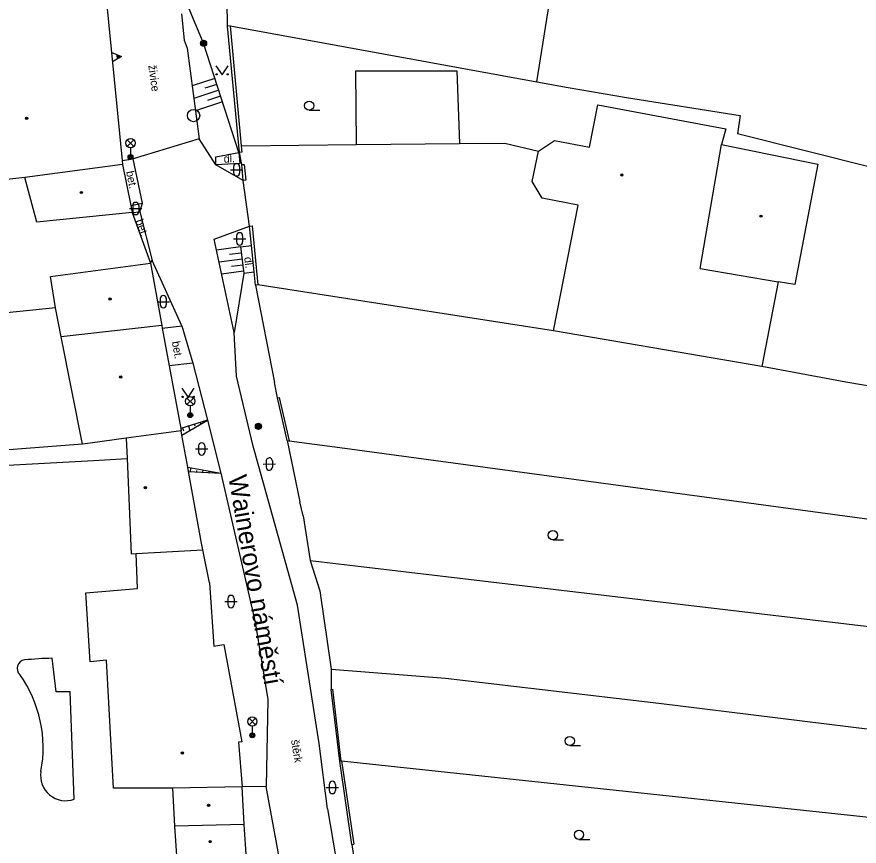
# Model space of a CAD drawing. Extents: x -596024 to -594475, y -1163820 to -1161957.
# Drawn here: x -595951 to -595882.6, y -1163122.3 to -1163055 of the extents above; entities that cross this region are included whole.
import ezdxf

# ---------------------------------------------------------------- set-up
doc = ezdxf.new("R2010")
doc.units = 0
for name, color, linetype in [('Level 10', 7, 'Continuous'), ('Level 11', 7, 'Continuous'), ('Level 14', 7, 'Continuous'), ('Level 15', 7, 'Continuous'), ('Level 25', 7, 'Continuous'), ('Level 26', 7, 'Continuous'), ('Level 27', 7, 'Continuous'), ('Level 33', 7, 'Continuous'), ('Level 36', 7, 'Continuous'), ('Level 39', 7, 'Continuous'), ('Level 40', 7, 'Continuous'), ('Level 5', 7, 'Continuous'), ('Level 50', 7, 'Continuous'), ('Level 7', 7, 'Continuous'), ('Level 8', 7, 'Continuous')]:
    doc.layers.add(name, color=color, linetype=linetype)

msp = doc.modelspace()

# ---------------------------------------------------------------- linework, layer by layer
at = {"layer": 'Level 10'}
for points in [[(-595937.62, -1163054.72), (-595937.42, -1163056.88)], [(-595937.42, -1163056.88), (-595937.18, -1163057.52), (-595936.2, -1163064.88)], [(-595936.2, -1163064.88), (-595941.55, -1163066.52)], [(-595942.46, -1163066.64), (-595941.55, -1163066.52)], [(-595925.56, -1163145.76), (-595930.74, -1163117.5)]]:
    msp.add_lwpolyline(points, dxfattribs=at)
at = {"layer": 'Level 11'}
for points in [[(-595908.77, -1163060.27), (-595906.11, -1163043.6)], [(-595933.69, -1163055.71), (-595908.77, -1163060.27)], [(-595923.42, -1163065.35), (-595923.48, -1163059.37), (-595915.27, -1163059.37), (-595915.06, -1163065.27)], [(-595908.77, -1163060.27), (-595906.23, -1163060.71), (-595901.49, -1163061.53), (-595892.25, -1163063), (-595892.46, -1163064.48)], [(-595870.58, -1163069.98), (-595892.46, -1163064.48)], [(-595932.61, -1163068.26), (-595934.83, -1163066.99), (-595936.2, -1163064.88)], [(-595932.78, -1163065.45), (-595923.42, -1163065.35), (-595915.06, -1163065.27), (-595911.36, -1163065.23), (-595908.64, -1163065.9)], [(-595934.84, -1163066.35), (-595932.98, -1163066)], [(-595932.98, -1163066), (-595932.88, -1163066.9)], [(-595940.79, -1163070.1), (-595941.55, -1163066.52)], [(-595934.83, -1163066.99), (-595934.84, -1163066.35)], [(-595932.88, -1163066.9), (-595934.83, -1163066.99)], [(-595941.75, -1163070.3), (-595940.79, -1163070.1)], [(-595941.02, -1163070.82), (-595940.79, -1163070.1)], [(-595941.64, -1163070.86), (-595941.02, -1163070.82), (-595940.02, -1163074.78)], [(-595941.64, -1163070.86), (-595940.16, -1163075)], [(-595925.77, -1163119.3), (-595926.44, -1163114), (-595928.22, -1163102.78), (-595931.81, -1163089.86), (-595933.15, -1163084.16), (-595933.34, -1163080.62), (-595934.98, -1163073.05), (-595932.1, -1163071.98)], [(-595932.84, -1163073.66), (-595931.95, -1163073.55)], [(-595932.84, -1163073.66), (-595932.57, -1163075.79)], [(-595940.16, -1163075), (-595940.02, -1163074.78)], [(-595937.6, -1163080.08), (-595940.02, -1163074.78)], [(-595932.57, -1163075.79), (-595931.74, -1163075.68)], [(-595939.19, -1163080.26), (-595937.6, -1163080.08)], [(-595937.6, -1163080.08), (-595936.72, -1163083.1)], [(-595936.72, -1163083.1), (-595938.63, -1163083.33)], [(-595936.72, -1163083.1), (-595935.53, -1163087.74), (-595934.43, -1163092.04)], [(-595883.67, -1163084.66), (-595890.49, -1163083.39)], [(-595852.37, -1163089.97), (-595883.67, -1163084.66)], [(-595942.12, -1163089.21), (-595942.05, -1163090.86), (-595941.73, -1163098.59), (-595941.3, -1163098.57), (-595935.89, -1163098.26)], [(-595924.76, -1163089.96), (-595851.92, -1163099.82), (-595835.6, -1163101.24)], [(-595973.67, -1163107.88), (-595986.21, -1163109.1), (-595987.16, -1163096.08), (-595975.26, -1163095.13), (-595974.46, -1163101.96), (-595953.83, -1163100.37), (-595954.25, -1163091.53), (-595944.79, -1163091.01)], [(-595944.79, -1163091.01), (-595942.05, -1163090.86)], [(-595934.43, -1163092.04), (-595931.64, -1163104.16), (-595930.61, -1163110.43), (-595930.74, -1163117.5)], [(-595943.16, -1163117.64), (-595943.73, -1163107.24), (-595945.04, -1163107.37), (-595945.39, -1163101.77), (-595941.2, -1163101.41), (-595941.3, -1163098.57)], [(-595923.03, -1163099.62), (-595851.06, -1163108.13), (-595814.6, -1163109.99), (-595785.58, -1163110.13)], [(-595946.34, -1163118.53), (-595946.67, -1163109.8), (-595947.8, -1163109.8), (-595948.13, -1163107.08)], [(-595925.48, -1163107.98), (-595916.18, -1163108.7), (-595898.85, -1163110.73), (-595850.52, -1163116.69), (-595814.21, -1163118.19), (-595794.24, -1163117.76)], [(-595920.85, -1163115.82), (-595870.62, -1163121.18), (-595850.22, -1163123.44), (-595837.87, -1163123.72), (-595813.71, -1163124.36), (-595801.21, -1163123.91)], [(-595930.74, -1163117.5), (-595932.71, -1163117.53)], [(-595925.77, -1163119.3), (-595921.49, -1163144.47)], [(-595923.78, -1163122.2), (-595923.58, -1163123.66), (-595921.57, -1163138.62), (-595920.36, -1163138.68)]]:
    msp.add_lwpolyline(points, dxfattribs=at)
for centre, radius, start, end in [((-595947.401, -1163136.942), 29.871, 91.39793, 95.72303), ((-595950.278, -1163107.912), 0.7, 98.39061, 225.31823), ((-595959.064, -1163114.346), 10.199, 349.06681, 35.58965), ((-595947.039, -1163116.614), 2.039, 170.56112, 290.03601)]:
    msp.add_arc(centre, radius, start, end, dxfattribs=at)
at = {"layer": 'Level 14'}
for points in [[(-595932.98, -1163066), (-595935.84, -1163057.12), (-595937.84, -1163052.3)], [(-595932.57, -1163075.79), (-595933.34, -1163080.62)], [(-595935.53, -1163087.74), (-595937.69, -1163088.42)], [(-595937.6, -1163088.95), (-595935.53, -1163087.74)], [(-595937.12, -1163091.57), (-595934.43, -1163092.04)], [(-595937.06, -1163091.92), (-595934.43, -1163092.04)]]:
    msp.add_lwpolyline(points, dxfattribs=at)
at = {"layer": 'Level 15'}
for points in [[(-595934.92, -1163059.99), (-595936.77, -1163060.59)], [(-595934.76, -1163060.47), (-595935.73, -1163060.78)], [(-595934.61, -1163060.94), (-595936.64, -1163061.6)], [(-595934.3, -1163061.89), (-595936.5, -1163062.6)], [(-595934.46, -1163061.42), (-595935.51, -1163061.76)], [(-595932.84, -1163073.67), (-595934.79, -1163073.92)], [(-595932.78, -1163074.17), (-595933.73, -1163074.29)], [(-595932.71, -1163074.66), (-595934.58, -1163074.9)], [(-595932.59, -1163075.65), (-595934.37, -1163075.88)], [(-595932.65, -1163075.16), (-595933.56, -1163075.27)], [(-595936.11, -1163087.92), (-595936.07, -1163088.06)], [(-595937.54, -1163088.37), (-595937.47, -1163088.6)], [(-595937.07, -1163088.22), (-595936.96, -1163088.57)], [(-595936.59, -1163088.07), (-595936.55, -1163088.19)], [(-595936.89, -1163091.93), (-595936.88, -1163091.61)], [(-595936.39, -1163091.95), (-595936.39, -1163091.82)], [(-595935.89, -1163091.97), (-595935.88, -1163091.79)], [(-595935.39, -1163092), (-595935.39, -1163091.93)], [(-595934.89, -1163092.02), (-595934.89, -1163091.96)]]:
    msp.add_lwpolyline(points, dxfattribs=at)
at = {"layer": 'Level 25'}
for centre, radius in [((-595935.84, -1163057.12), 0.25), ((-595935.84, -1163057.12), 0.2), ((-595935.84, -1163057.12), 0.15), ((-595935.84, -1163057.12), 0.1), ((-595935.84, -1163057.12), 0.05), ((-595931.38, -1163088.24), 0.25), ((-595931.38, -1163088.24), 0.2), ((-595931.38, -1163088.24), 0.15), ((-595931.38, -1163088.24), 0.1), ((-595931.38, -1163088.24), 0.05)]:
    msp.add_circle(centre, radius, dxfattribs=at)
at = {"layer": 'Level 26'}
for p, q in [((-595942.875, -1163058.054), (-595942.847, -1163058.403)), ((-595942.823, -1163058.075), (-595942.799, -1163058.374)), ((-595942.772, -1163058.096), (-595942.752, -1163058.345)), ((-595942.72, -1163058.116), (-595942.704, -1163058.316)), ((-595942.668, -1163058.137), (-595942.656, -1163058.287))]:
    msp.add_line(p, q, dxfattribs=at)
msp.add_lwpolyline([(-595943.29, -1163057.886), (-595942.512, -1163058.2), (-595943.23, -1163058.634)], dxfattribs=at)
at = {"layer": 'Level 27'}
msp.add_circle((-595936.65, -1163063), 0.5, dxfattribs=at)
at = {"layer": 'Level 33'}
for p, q in [((-595942.035, -1163065.5), (-595941.505, -1163064.97)), ((-595942.035, -1163064.97), (-595941.505, -1163065.5)), ((-595941.77, -1163065.61), (-595941.77, -1163066.36)), ((-595937.185, -1163086.47), (-595936.655, -1163085.94)), ((-595937.185, -1163085.94), (-595936.655, -1163086.47)), ((-595936.92, -1163086.58), (-595936.92, -1163087.33)), ((-595932.145, -1163112.48), (-595931.615, -1163111.95)), ((-595932.145, -1163111.95), (-595931.615, -1163112.48)), ((-595931.88, -1163112.59), (-595931.88, -1163113.34))]:
    msp.add_line(p, q, dxfattribs=at)
for centre, radius in [((-595941.77, -1163065.235), 0.375), ((-595941.77, -1163066.36), 0.2), ((-595941.77, -1163066.36), 0.145), ((-595941.77, -1163066.36), 0.0876), ((-595936.92, -1163086.205), 0.375), ((-595936.92, -1163087.33), 0.2), ((-595936.92, -1163087.33), 0.145), ((-595936.92, -1163087.33), 0.0876), ((-595931.88, -1163112.215), 0.375), ((-595931.88, -1163113.34), 0.2), ((-595931.88, -1163113.34), 0.145), ((-595931.88, -1163113.34), 0.0876)]:
    msp.add_circle(centre, radius, dxfattribs=at)
at = {"layer": 'Level 36'}
for p, q in [((-595927.26, -1163062.565), (-595926.385, -1163062.565)), ((-595933.656, -1163067.406), (-595932.656, -1163067.406)), ((-595933.406, -1163067.156), (-595933.406, -1163067.656)), ((-595932.906, -1163067.156), (-595932.906, -1163067.656)), ((-595941.846, -1163070.546), (-595940.846, -1163070.546)), ((-595941.596, -1163070.296), (-595941.596, -1163070.796)), ((-595941.096, -1163070.296), (-595941.096, -1163070.796)), ((-595933.166, -1163072.766), (-595933.166, -1163073.266)), ((-595932.666, -1163072.766), (-595932.666, -1163073.266)), ((-595933.416, -1163073.016), (-595932.416, -1163073.016)), ((-595939.616, -1163078.116), (-595938.616, -1163078.116)), ((-595939.366, -1163077.866), (-595939.366, -1163078.366)), ((-595938.866, -1163077.866), (-595938.866, -1163078.366)), ((-595936.246, -1163089.826), (-595936.246, -1163090.326)), ((-595935.746, -1163089.826), (-595935.746, -1163090.326)), ((-595936.496, -1163090.076), (-595935.496, -1163090.076)), ((-595930.996, -1163091.315), (-595929.996, -1163091.297)), ((-595930.751, -1163091.061), (-595930.742, -1163091.561)), ((-595930.251, -1163091.052), (-595930.242, -1163091.552)), ((-595907.46, -1163097.455), (-595906.585, -1163097.455)), ((-595933.856, -1163102.226), (-595933.856, -1163102.726)), ((-595933.356, -1163102.226), (-595933.356, -1163102.726)), ((-595934.106, -1163102.476), (-595933.106, -1163102.476)), ((-595906.09, -1163114.175), (-595905.215, -1163114.175)), ((-595925.626, -1163117.326), (-595925.626, -1163117.826)), ((-595925.126, -1163117.326), (-595925.126, -1163117.826)), ((-595925.876, -1163117.576), (-595924.876, -1163117.576)), ((-595905.34, -1163121.795), (-595904.465, -1163121.795))]:
    msp.add_line(p, q, dxfattribs=at)
for points in [[(-595934.83, -1163058.95), (-595934.33, -1163059.7), (-595933.83, -1163058.95)], [(-595937.59, -1163085.15), (-595937.09, -1163085.9), (-595936.59, -1163085.15)]]:
    msp.add_lwpolyline(points, dxfattribs=at)
for centre, radius in [((-595934.78, -1163059.65), 0.05), ((-595933.881, -1163059.65), 0.05), ((-595927.26, -1163062.19), 0.375), ((-595937.54, -1163085.85), 0.05), ((-595936.641, -1163085.85), 0.05), ((-595907.46, -1163097.08), 0.375), ((-595906.09, -1163113.8), 0.375), ((-595905.34, -1163121.42), 0.375)]:
    msp.add_circle(centre, radius, dxfattribs=at)
for centre, start, end in [((-595933.156, -1163067.156), 0, 180), ((-595933.156, -1163067.656), 180, 0), ((-595941.346, -1163070.296), 0, 180), ((-595941.346, -1163070.796), 180, 0), ((-595932.916, -1163072.766), 0, 180), ((-595932.916, -1163073.266), 180, 0), ((-595939.116, -1163077.866), 0, 180), ((-595939.116, -1163078.366), 180, 0), ((-595935.996, -1163089.826), 0, 180), ((-595935.996, -1163090.326), 180, 0), ((-595930.5, -1163091.056), 1.03344, 181.03344), ((-595930.491, -1163091.556), 181.03344, 1.03344), ((-595933.606, -1163102.226), 0, 180), ((-595933.606, -1163102.726), 180, 0), ((-595925.376, -1163117.326), 0, 180), ((-595925.376, -1163117.826), 180, 0)]:
    msp.add_arc(centre, 0.25, start, end, dxfattribs=at)
at = {"layer": 'Level 39'}
for centre, radius in [((-595950.21, -1163063.22), 0.09), ((-595950.21, -1163063.22), 0.0398), ((-595901.86, -1163067.83), 0.09), ((-595901.86, -1163067.83), 0.0398), ((-595945.76, -1163069.25), 0.09), ((-595945.76, -1163069.25), 0.0398), ((-595890.55, -1163071.17), 0.09), ((-595890.55, -1163071.17), 0.0398), ((-595943.43, -1163077.9), 0.09), ((-595943.43, -1163077.9), 0.0398), ((-595942.57, -1163084.23), 0.09), ((-595942.57, -1163084.23), 0.0398), ((-595940.56, -1163093.23), 0.09), ((-595940.56, -1163093.23), 0.0398), ((-595937.56, -1163114.77), 0.09), ((-595937.56, -1163114.77), 0.0398), ((-595935.43, -1163119.03), 0.09), ((-595935.43, -1163119.03), 0.0398), ((-595935.3, -1163121.98), 0.09), ((-595935.3, -1163121.98), 0.0398)]:
    msp.add_circle(centre, radius, dxfattribs=at)
at = {"layer": 'Level 5'}
for points in [[(-595943.99, -1163051.01), (-595942.46, -1163066.64), (-595942.43, -1163066.98)], [(-595904.48, -1163065.56), (-595903.81, -1163062.12)], [(-595903.81, -1163062.12), (-595893.4, -1163064.07)], [(-595893.4, -1163064.07), (-595893.75, -1163065.36)], [(-595908.64, -1163065.9), (-595907.34, -1163065.02)], [(-595907.34, -1163065.02), (-595904.48, -1163065.56)], [(-595895.49, -1163075.42), (-595893.75, -1163065.36)], [(-595893.75, -1163065.36), (-595885.93, -1163066.94)], [(-595909.15, -1163068.35), (-595908.64, -1163065.9)], [(-595942.43, -1163066.98), (-595950.35, -1163068.03)], [(-595942.43, -1163066.98), (-595941.75, -1163070.3), (-595941.64, -1163070.86)], [(-595885.93, -1163066.94), (-595887.81, -1163076.72)], [(-595950.35, -1163068.03), (-595957.7, -1163068.85)], [(-595949.39, -1163071.65), (-595950.35, -1163068.03)], [(-595908.34, -1163069.72), (-595909.15, -1163068.35)], [(-595905.42, -1163070.28), (-595908.34, -1163069.72)], [(-595941.64, -1163070.86), (-595949.39, -1163071.65)], [(-595907.41, -1163080.47), (-595905.42, -1163070.28)], [(-595948.28, -1163076.08), (-595940.16, -1163075)], [(-595940.16, -1163075), (-595939.23, -1163080.04)], [(-595895.49, -1163075.42), (-595889.15, -1163076.51)], [(-595947.86, -1163078.61), (-595948.28, -1163076.08)], [(-595889.15, -1163076.51), (-595890.49, -1163083.39)], [(-595887.81, -1163076.72), (-595889.15, -1163076.51)], [(-595947.4, -1163080.98), (-595947.86, -1163078.61)], [(-595939.23, -1163080.04), (-595947.4, -1163080.98)], [(-595939.23, -1163080.04), (-595939.19, -1163080.26), (-595938.63, -1163083.33), (-595937.69, -1163088.42), (-595937.66, -1163088.6)], [(-595945.66, -1163089.7), (-595947.4, -1163080.98)], [(-595890.49, -1163083.39), (-595907.41, -1163080.47)], [(-595937.66, -1163088.6), (-595942.12, -1163089.21), (-595945.05, -1163089.62)], [(-595936, -1163097.74), (-595937.06, -1163091.92), (-595937.12, -1163091.57), (-595937.6, -1163088.95), (-595937.66, -1163088.6)], [(-595945.05, -1163089.62), (-595945.66, -1163089.7)], [(-595935.35, -1163100.95), (-595935.89, -1163098.26), (-595936, -1163097.74)], [(-595935.35, -1163100.95), (-595935, -1163106.11), (-595934.19, -1163105.96), (-595932.72, -1163113.87), (-595932.99, -1163113.9)], [(-595932.99, -1163113.9), (-595932.71, -1163117.53)], [(-595938.37, -1163117.64), (-595943.16, -1163117.64)], [(-595932.71, -1163117.53), (-595938.37, -1163117.64)], [(-595938.37, -1163117.64), (-595938.19, -1163120.71)], [(-595932.55, -1163120.59), (-595932.71, -1163117.53)], [(-595932.55, -1163120.59), (-595938.19, -1163120.71)], [(-595938.19, -1163120.71), (-595938.02, -1163123.5)], [(-595932.35, -1163123.39), (-595932.55, -1163120.59)]]:
    msp.add_lwpolyline(points, dxfattribs=at)
at = {"layer": 'Level 7'}
for points in [[(-595933.89, -1163055.73), (-595934.07, -1163041.39), (-595906.11, -1163043.6)], [(-595933.69, -1163055.71), (-595933.89, -1163055.73)], [(-595932.73, -1163065.97), (-595932.93, -1163065.99), (-595933.89, -1163055.73)], [(-595933.69, -1163055.71), (-595932.78, -1163065.45), (-595932.73, -1163065.97)], [(-595932.41, -1163068.24), (-595932.61, -1163068.26), (-595932.73, -1163066.98), (-595932.53, -1163066.96)], [(-595932.53, -1163066.96), (-595932.41, -1163068.24)], [(-595931.95, -1163073.55), (-595932.1, -1163071.98), (-595931.9, -1163071.96)], [(-595931.9, -1163071.96), (-595931.43, -1163076.76)], [(-595931.43, -1163076.76), (-595931.63, -1163076.78), (-595931.74, -1163075.68), (-595931.95, -1163073.55)], [(-595931.63, -1163076.78), (-595930.08, -1163084.69)], [(-595907.41, -1163080.47), (-595931.43, -1163076.76)], [(-595947.86, -1163078.61), (-595977.95, -1163081.69), (-596005.58, -1163084.22)], [(-595929.84, -1163085.92), (-595929.69, -1163085.89)], [(-595929.05, -1163089.39), (-595929.84, -1163085.92)], [(-595929.69, -1163085.89), (-595928.89, -1163089.41)], [(-595945.66, -1163089.7), (-595982.61, -1163092.52), (-595993.41, -1163095.02), (-595995.66, -1163095.54), (-595999.75, -1163098.3)], [(-595929.05, -1163089.39), (-595928.03, -1163094.37)], [(-595929.05, -1163089.39), (-595928.89, -1163089.41), (-595924.76, -1163089.96)], [(-595927.76, -1163095.5), (-595927.19, -1163099.14)], [(-595927.19, -1163099.14), (-595923.03, -1163099.62)], [(-595927.19, -1163099.14), (-595926.4, -1163101.6)], [(-595925.46, -1163109.61), (-595925.36, -1163109.6)], [(-595924.78, -1163115.44), (-595925.46, -1163109.61)], [(-595925.36, -1163109.6), (-595924.68, -1163115.43)], [(-595924.63, -1163115.42), (-595924.68, -1163115.43), (-595924.78, -1163115.44)], [(-595923.78, -1163122.2), (-595924.78, -1163115.44)], [(-595924.63, -1163115.42), (-595920.85, -1163115.82)], [(-595924.63, -1163115.42), (-595923.63, -1163122.18)], [(-595923.78, -1163122.2), (-595923.63, -1163122.18)]]:
    msp.add_lwpolyline(points, dxfattribs=at)
at = {"layer": 'Level 8'}
for points in [[(-595932.73, -1163066.98), (-595932.93, -1163065.99)], [(-595932.1, -1163071.98), (-595932.61, -1163068.26)], [(-595929.84, -1163085.92), (-595930.08, -1163084.69)], [(-595927.76, -1163095.5), (-595928.03, -1163094.37)], [(-595926.4, -1163101.6), (-595925.48, -1163107.98), (-595925.46, -1163109.61)]]:
    msp.add_lwpolyline(points, dxfattribs=at)

# ---------------------------------------------------------------- texts
at = {"layer": 'Level 40'}
for s, rotation, p in [('živice', 277.77458, (-595940.33, -1163058.93)), ('dl.', 2.64254, (-595934.19, -1163066.83)), ('bet.', 281.5086, (-595942.14, -1163067.56)), ('bet.', 289.67136, (-595941.38, -1163071.54)), ('dl.', 277.22431, (-595932.54, -1163074.52)), ('bet.', 280, (-595938.41, -1163081.38)), ('štěrk', 279.01458, (-595928.73, -1163113.74))]:
    msp.add_text(s, height=0.65, rotation=rotation, dxfattribs=at).set_placement(p)
at = {"layer": 'Level 50'}
msp.add_text('Wainerovo náměstí', height=1.5, rotation=279.8179, dxfattribs=at).set_placement((-595933.831, -1163092.337))

doc.saveas('drawing.dxf')
